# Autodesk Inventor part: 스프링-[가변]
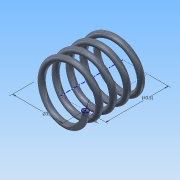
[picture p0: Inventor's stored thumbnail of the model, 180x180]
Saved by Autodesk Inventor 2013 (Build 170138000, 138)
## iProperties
Created: 2015-03
Part Number: 스프링-[가변]
Material: 강철, 탄소
Document SubType Name: Modeling
Designer: Administrator
Density: 7.87 g/cm^3
Mass: 47.9935 g
Surface Area: 62.0176 cm^2
Volume: 6.09829 cm^3
Author: Administrator
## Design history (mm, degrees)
sketch "스케치1"
  geometry: L1 (0, 0)-(17.5, 0); L2 (17.5, 0)-(17.5, 43.5); L3 (17.5, 43.5)-(0, 43.5); L4 (0, 43.5)-(0, 0); C1 r 2 at (17.5, 0)
  constraints: 8 end point, 2 parallel, 1 centre point, 1 coincident, 1 horizontal, 1 perpendicular
  dimensions: "d0" = 4 diameter of C1; "d2" = 35 diameter of L2 L4; "d3" = 43.5 distance of L1.end L2.end (derived)
feature "코일1" sketch "스케치1" pitch "d4" = 10; turns "d6" = 4.5; dims "d5" = 43.5 (= d3), "d7" = 0, angle "d8" = 90 deg, angle "d9" = 90 deg, "d10" = 0, "d11" = 0
sketch "스케치2"
  geometry: L1 (-19.5, 0)-(-15.5, 0) reference; 1 further point
  constraints: 1 horizontal alignment
extrude "돌출1" cut sketch "스케치2" stored distance "d12" = 10; taper "d13" = 0 deg
node "작업 평면1"
sketch "스케치3"
  geometry: L1 (15.5, 0)-(19.5, 0) reference; 1 further point
  constraints: 1 horizontal alignment
extrude "돌출2" cut sketch "스케치3" stored distance "d15" = 10; taper "d16" = 0 deg
node "솔리드1"
node "절단 모서리 투영1"
node "절단 모서리 투영2"
other parameters: "d14" = 43.5 (= d3)
